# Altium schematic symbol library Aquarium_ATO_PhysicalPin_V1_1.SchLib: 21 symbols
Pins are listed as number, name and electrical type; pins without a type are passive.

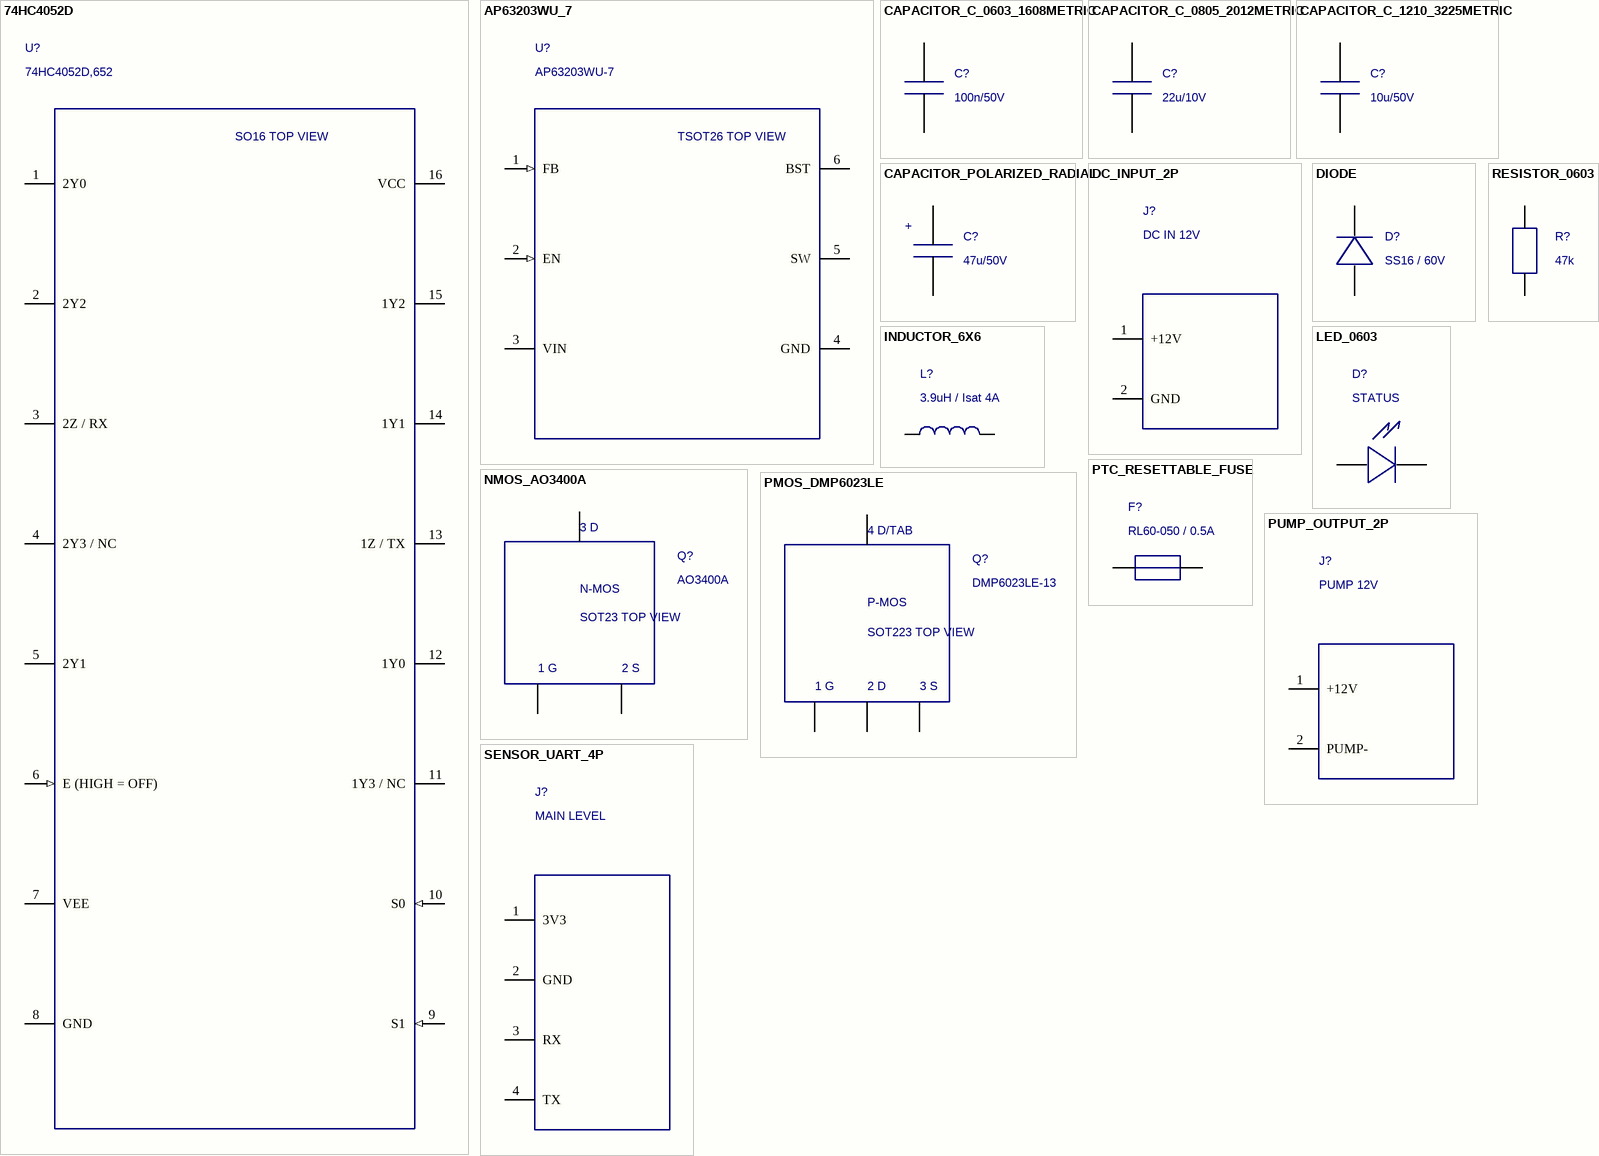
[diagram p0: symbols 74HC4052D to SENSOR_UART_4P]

## 74HC4052D
designator U?, comment 74HC4052D,652
74HC4052D,652; package SO16 (SOT109-1); footprint SOIC-16_P1.27
footprint SOIC-16_P1.27
pins: 1 2Y0, 2 2Y2, 3 2Z / RX, 4 2Y3 / NC, 5 2Y1, 6 E (HIGH = OFF) (in), 7 VEE (power), 8 GND (power), 9 S1 (in), 10 S0 (in), 11 1Y3 / NC, 12 1Y0, 13 1Z / TX, 14 1Y1, 15 1Y2, 16 VCC (power)

## AP63203WU_7
designator U?, comment AP63203WU-7
AP63203WU-7; package TSOT26; footprint TSOT-23-6_P0.95
footprint TSOT-23-6_P0.95
pins: 1 FB (in), 2 EN (in), 3 VIN (power), 4 GND (power), 5 SW, 6 BST

## CAPACITOR_C_0603_1608METRIC
designator C?, comment 100n/50V
100n/50V; footprint C_0603_1608Metric
footprint C_0603_1608Metric
pins: 1, 2

## CAPACITOR_C_0805_2012METRIC
designator C?, comment 22u/10V
22u/10V; footprint C_0805_2012Metric
footprint C_0805_2012Metric
pins: 1, 2

## CAPACITOR_C_1210_3225METRIC
designator C?, comment 10u/50V
10u/50V; footprint C_1210_3225Metric
footprint C_1210_3225Metric
pins: 1, 2

## CAPACITOR_POLARIZED_RADIAL
designator C?, comment 47u/50V
47u/50V; footprint CP_RADIAL_D8.0_P3.50
footprint CP_RADIAL_D8.0_P3.50
pins: 1, 2

## DC_INPUT_2P
designator J?, comment DC IN 12V
DC IN 12V; footprint TB_2P_P5.08
footprint TB_2P_P5.08
pins: 1 +12V, 2 GND

## DIODE
designator D?, comment SS16 / 60V
SS16 / 60V; package SMA; footprint D_SMA
footprint D_SMA
pins: 1 K, 2 A

## INDUCTOR_6X6
designator L?, comment 3.9uH / Isat 4A
3.9uH / Isat 4A; footprint IND_SMD_6.0x6.0
footprint IND_SMD_6.0x6.0
pins: 1, 2

## LED_0603
designator D?, comment STATUS
STATUS; footprint LED_0603_1608Metric
footprint LED_0603_1608Metric
pins: 1 K, 2 A

## NMOS_AO3400A
designator Q?, comment AO3400A
AO3400A; package SOT23; footprint SOT-23-3
footprint SOT-23-3
pins: 1 G, 2 S, 3 D

## PMOS_DMP6023LE
designator Q?, comment DMP6023LE-13
DMP6023LE-13; package SOT223 (tab/pad 4 = drain); footprint SOT-223-4
footprint SOT-223-4
pins: 1 G, 2 D, 3 S, 4 D / TAB

## PTC_RESETTABLE_FUSE
designator F?, comment RL60-050 / 0.5A
RL60-050 / 0.5A; package Radial leaded PPTC; footprint PPTC_RADIAL_P5.10_D8.0
footprint PPTC_RADIAL_P5.10_D8.0
pins: 1, 2

## PUMP_OUTPUT_2P
designator J?, comment PUMP 12V
PUMP 12V; footprint TB_2P_P5.08
footprint TB_2P_P5.08
pins: 1 +12V, 2 PUMP-

## RESISTOR_0603
designator R?, comment 47k
47k; footprint R_0603_1608Metric
footprint R_0603_1608Metric
pins: 1, 2

## SENSOR_UART_4P
designator J?, comment MAIN LEVEL
MAIN LEVEL; footprint HDR_1x4_P2.54
footprint HDR_1x4_P2.54
pins: 1 3V3, 2 GND, 3 RX, 4 TX

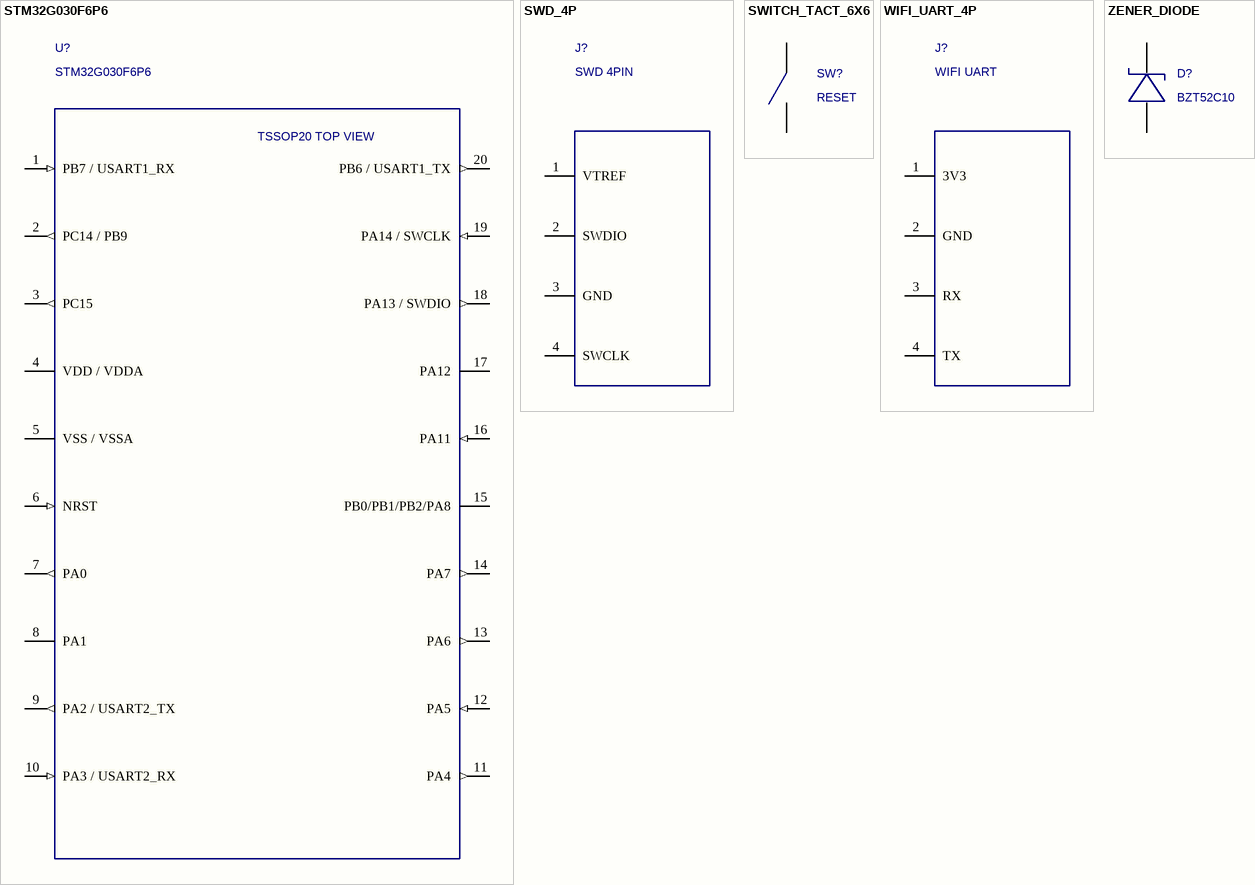
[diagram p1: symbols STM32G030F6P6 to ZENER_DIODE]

## STM32G030F6P6
designator U?
STM32G030F6P6; package TSSOP20; footprint TSSOP-20_P0.65
footprint TSSOP-20_P0.65
pins: 1 PB7 / USART1_RX (in), 2 PC14 / PB9 (out), 3 PC15 (out), 4 VDD / VDDA (power), 5 VSS / VSSA (power), 6 NRST (in), 7 PA0 (out), 8 PA1, 9 PA2 / USART2_TX (out), 10 PA3 / USART2_RX (in), 11 PA4 (out), 12 PA5 (in), 13 PA6 (out), 14 PA7 (out), 15 PB0/PB1/PB2/PA8, 16 PA11 (in), 17 PA12, 18 PA13 / SWDIO (out), 19 PA14 / SWCLK (in), 20 PB6 / USART1_TX (out)

## SWD_4P
designator J?, comment SWD 4PIN
SWD 4PIN; footprint HDR_1x4_P2.54
footprint HDR_1x4_P2.54
pins: 1 VTREF, 2 SWDIO, 3 GND, 4 SWCLK

## SWITCH_TACT_6X6
designator SW?, comment RESET
RESET; footprint SW_TACT_6x6_4P
footprint SW_TACT_6x6_4P
pins: 1, 2

## WIFI_UART_4P
designator J?, comment WIFI UART
WIFI UART; footprint HDR_1x4_P2.54
footprint HDR_1x4_P2.54
pins: 1 3V3, 2 GND, 3 RX, 4 TX

## ZENER_DIODE
designator D?, comment BZT52C10
BZT52C10; package SOD-123; footprint SOD-123
footprint SOD-123
pins: 1 K, 2 A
